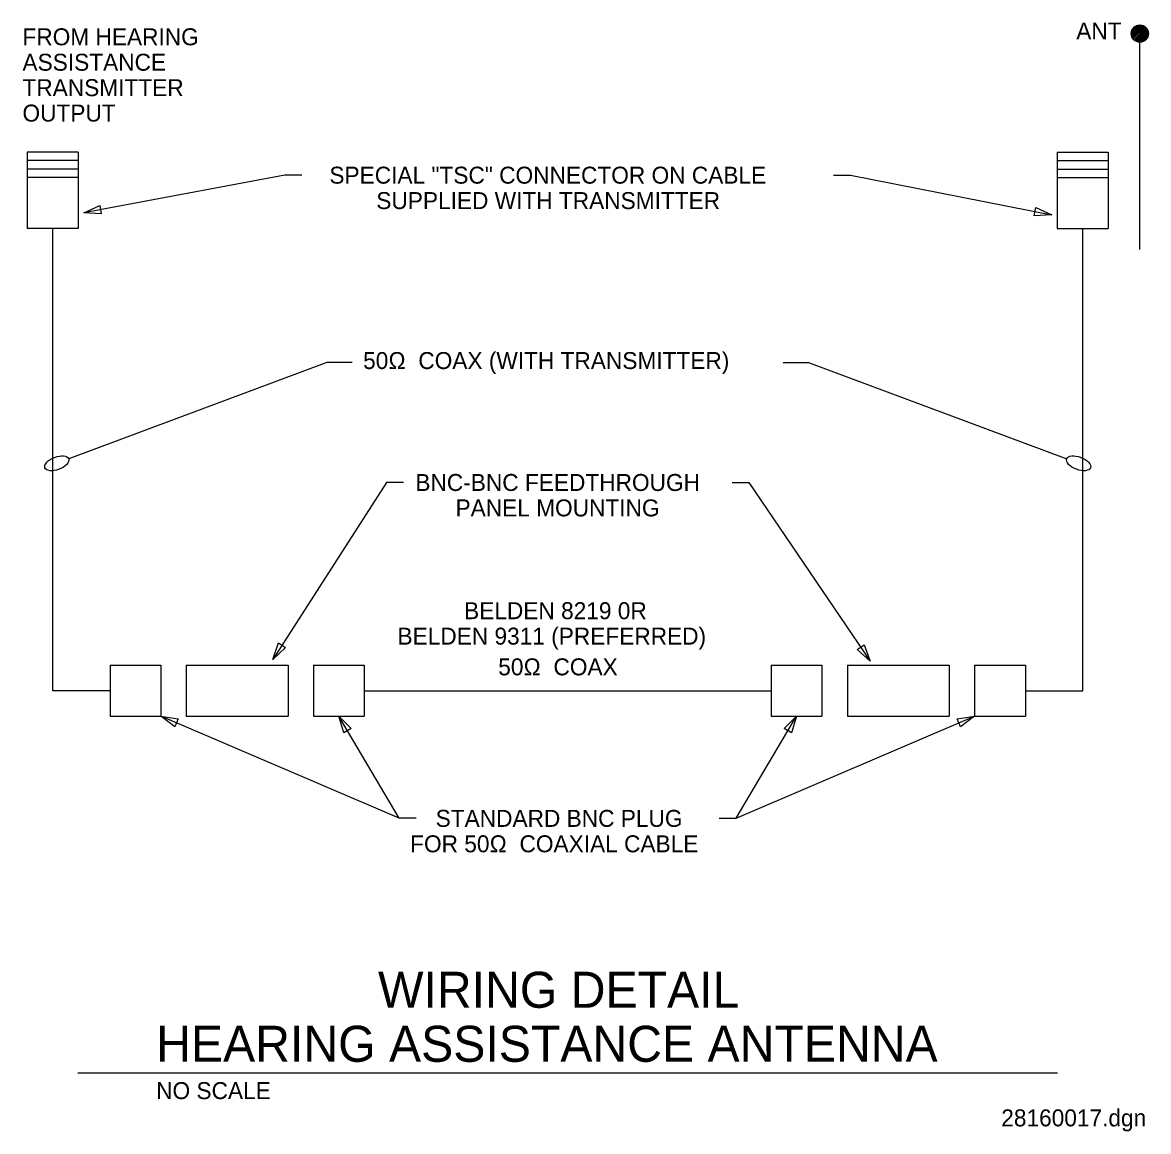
# Model space of a CAD drawing. Extents: x 10131.2 to 10175.5, y 10141.1 to 10184.8.
import ezdxf

# ---------------------------------------------------------------- set-up
doc = ezdxf.new("R2010")
doc.units = 0
doc.layers.add('G-ANNO-TEXT', color=7, linetype='Continuous')
doc.layers.add('G-DETL-LINE', color=7, linetype='Continuous')

msp = doc.modelspace()

# ---------------------------------------------------------------- linework, layer by layer
at = {"layer": 'G-ANNO-TEXT'}
for p, q in [((10141.485, 10178.752), (10133.581, 10177.267)), ((10142.151, 10178.752), (10141.485, 10178.752)), ((10163.07, 10178.752), (10163.737, 10178.752)), ((10163.737, 10178.752), (10171.645, 10177.193)), ((10145.482, 10166.668), (10141.015, 10159.712)), ((10146.149, 10166.668), (10145.482, 10166.668)), ((10159.073, 10166.668), (10159.739, 10166.668)), ((10159.739, 10166.668), (10164.508, 10159.637)), ((10145.981, 10153.472), (10136.611, 10157.482)), ((10145.981, 10153.472), (10143.611, 10157.482)), ((10159.241, 10153.472), (10161.611, 10157.482)), ((10159.241, 10153.472), (10168.611, 10157.482)), ((10146.647, 10153.472), (10145.981, 10153.472)), ((10146.647, 10153.472), (10145.981, 10153.472)), ((10158.574, 10153.472), (10159.241, 10153.472)), ((10158.574, 10153.472), (10159.241, 10153.472)), ((10133.348, 10143.456), (10171.873, 10143.456))]:
    msp.add_line(p, q, dxfattribs=at)
for points in [[(10134.267, 10177.227), (10133.581, 10177.267), (10134.205, 10177.554)], [(10171.023, 10177.486), (10171.645, 10177.193), (10170.959, 10177.158)], [(10141.516, 10160.182), (10141.015, 10159.712), (10141.235, 10160.363)], [(10164.272, 10160.282), (10164.508, 10159.637), (10163.996, 10160.095)], [(10137.158, 10157.066), (10136.611, 10157.482), (10137.289, 10157.373)], [(10143.806, 10156.823), (10143.611, 10157.482), (10144.093, 10156.993)], [(10161.128, 10156.993), (10161.611, 10157.482), (10161.415, 10156.823)], [(10167.932, 10157.373), (10168.611, 10157.482), (10168.063, 10157.066)]]:
    msp.add_lwpolyline(points, close=True, dxfattribs=at)
for points in [[(10144.138, 10171.391), (10143.138, 10171.391), (10132.986, 10167.597)], [(10161.083, 10171.391), (10162.083, 10171.391), (10172.235, 10167.597)]]:
    msp.add_lwpolyline(points, dxfattribs=at)
for centre, major_axis in [((10132.518, 10167.422), (-0.468, -0.175)), ((10172.703, 10167.422), (0.468, -0.175))]:
    msp.add_ellipse(centre, major_axis=major_axis, ratio=0.5, dxfattribs=at)
at = {"layer": 'G-DETL-LINE'}
for p, q in [((10174.774, 10184.333), (10175.098, 10184.658)), ((10174.776, 10184.276), (10175.155, 10184.655)), ((10174.784, 10184.402), (10175.029, 10184.648)), ((10174.786, 10184.227), (10175.204, 10184.645)), ((10174.801, 10184.184), (10175.248, 10184.63)), ((10174.821, 10184.145), (10175.287, 10184.61)), ((10174.832, 10184.509), (10174.922, 10184.599)), ((10174.843, 10184.108), (10175.323, 10184.588)), ((10174.873, 10184.079), (10175.353, 10184.559)), ((10174.904, 10184.051), (10175.382, 10184.529)), ((10174.939, 10184.027), (10175.404, 10184.492)), ((10174.978, 10184.007), (10175.424, 10184.453)), ((10175.022, 10183.992), (10175.44, 10184.41)), ((10175.071, 10183.982), (10175.45, 10184.361)), ((10175.113, 10175.825), (10175.113, 10183.981)), ((10175.127, 10183.98), (10175.452, 10184.304)), ((10175.196, 10183.99), (10175.442, 10184.235)), ((10175.304, 10184.038), (10175.394, 10184.128)), ((10131.356, 10179.659), (10131.356, 10176.659)), ((10133.356, 10179.659), (10131.356, 10179.659)), ((10133.356, 10179.659), (10133.356, 10176.659)), ((10171.865, 10179.659), (10171.865, 10176.659)), ((10171.865, 10179.659), (10173.865, 10179.659)), ((10173.865, 10179.659), (10173.865, 10176.659)), ((10133.356, 10179.326), (10131.356, 10179.326)), ((10171.865, 10179.326), (10173.865, 10179.326)), ((10133.356, 10178.993), (10131.356, 10178.993)), ((10133.356, 10178.659), (10131.356, 10178.659)), ((10171.865, 10178.993), (10173.865, 10178.993)), ((10171.865, 10178.659), (10173.865, 10178.659)), ((10133.356, 10176.659), (10131.356, 10176.659)), ((10171.865, 10176.659), (10173.865, 10176.659)), ((10134.611, 10159.482), (10134.611, 10157.482)), ((10134.611, 10159.482), (10136.611, 10159.482)), ((10136.611, 10159.482), (10136.611, 10157.482)), ((10137.611, 10159.482), (10137.611, 10157.482)), ((10137.611, 10159.482), (10141.611, 10159.482)), ((10141.611, 10159.482), (10141.611, 10157.482)), ((10142.611, 10159.482), (10142.611, 10157.482)), ((10142.611, 10159.482), (10144.611, 10159.482)), ((10144.611, 10159.482), (10144.611, 10157.482)), ((10160.611, 10159.482), (10160.611, 10157.482)), ((10160.611, 10159.482), (10162.611, 10159.482)), ((10162.611, 10159.482), (10162.611, 10157.482)), ((10163.611, 10159.482), (10163.611, 10157.482)), ((10163.611, 10159.482), (10167.611, 10159.482)), ((10167.611, 10159.482), (10167.611, 10157.482)), ((10168.611, 10159.482), (10168.611, 10157.482)), ((10168.611, 10159.482), (10170.611, 10159.482)), ((10170.611, 10159.482), (10170.611, 10157.482)), ((10170.611, 10159.482), (10170.611, 10157.482)), ((10144.611, 10158.482), (10160.611, 10158.482)), ((10134.611, 10157.482), (10136.611, 10157.482)), ((10137.611, 10157.482), (10141.611, 10157.482)), ((10142.611, 10157.482), (10144.611, 10157.482)), ((10160.611, 10157.482), (10162.611, 10157.482)), ((10163.611, 10157.482), (10167.611, 10157.482)), ((10168.611, 10157.482), (10170.611, 10157.482))]:
    msp.add_line(p, q, dxfattribs=at)
for points in [[(10134.611, 10158.482), (10132.356, 10158.482), (10132.356, 10176.659)], [(10170.611, 10158.482), (10172.865, 10158.482), (10172.865, 10176.659)]]:
    msp.add_lwpolyline(points, dxfattribs=at)
msp.add_circle((10175.113, 10184.319), 0.339, dxfattribs=at)

# ---------------------------------------------------------------- texts
at = {"layer": 'G-ANNO-TEXT'}
for s, height, p in [('ANT', 0.6667, (10172.612, 10184.088)), ('FROM HEARING', 0.66667, (10131.167, 10183.86)), ('ASSISTANCE', 0.6667, (10131.167, 10182.86)), ('TRANSMITTER', 0.66667, (10131.167, 10181.86)), ('OUTPUT', 0.6667, (10131.167, 10180.86)), ('SPECIAL "TSC" CONNECTOR ON CABLE', 0.66667, (10143.238, 10178.419)), ('SUPPLIED WITH TRANSMITTER', 0.66667, (10145.083, 10177.419)), ('50Ω  COAX (WITH TRANSMITTER)', 0.66667, (10144.564, 10171.129)), ('BNC-BNC FEEDTHROUGH', 0.66667, (10146.619, 10166.335)), ('PANEL MOUNTING', 0.66667, (10148.199, 10165.335)), ('BELDEN 8219 0R', 0.66667, (10148.535, 10161.293)), ('BELDEN 9311 (PREFERRED)', 0.66667, (10145.916, 10160.293)), ('50Ω  COAX', 0.6667, (10149.879, 10159.085)), ('STANDARD BNC PLUG', 0.66667, (10147.417, 10153.127)), ('FOR 50Ω  COAXIAL CABLE', 0.66667, (10146.414, 10152.127)), ('WIRING DETAIL', 1.41667, (10145.152, 10146.013)), ('HEARING ASSISTANCE ANTENNA', 1.41667, (10136.425, 10143.888)), ('NO SCALE', 0.6667, (10136.425, 10142.421)), ('28160017.dgn', 0.66667, (10169.662, 10141.35))]:
    msp.add_text(s, height=height, dxfattribs=at).set_placement(p)

doc.saveas('drawing.dxf')
